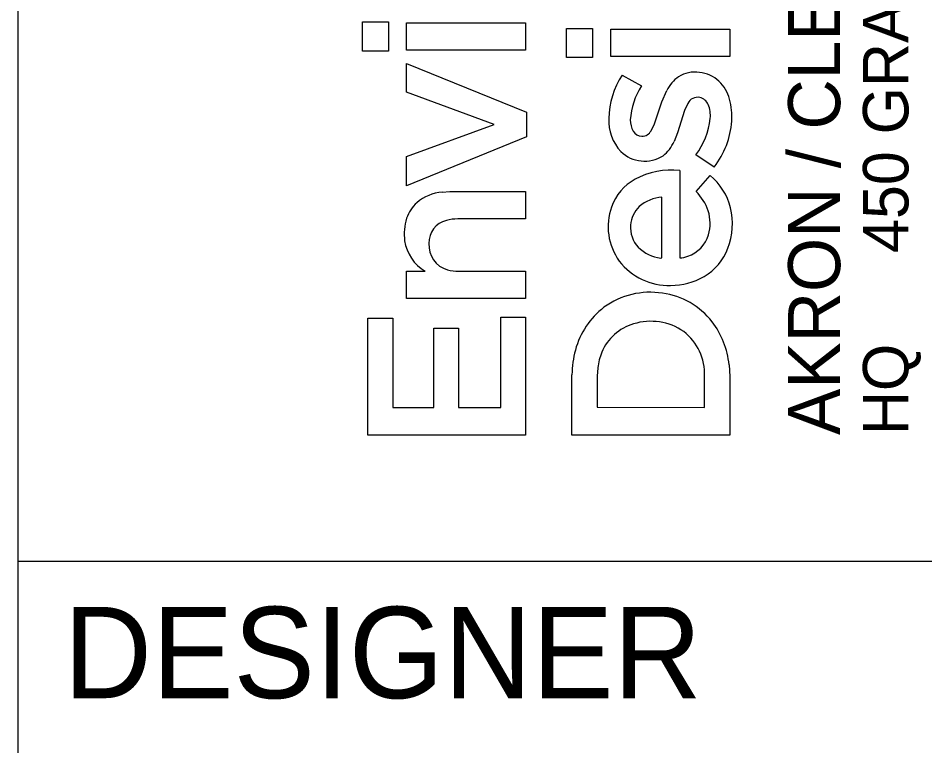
# Model space of a CAD drawing. Extents: x 0 to 34, y 0 to 22.
# Drawn here: x 32 to 32.993, y 2.798 to 3.594 of the extents above; entities that cross this region are included whole.
import ezdxf

# ---------------------------------------------------------------- set-up
doc = ezdxf.new("R2010")
doc.units = 0
doc.layers.add('SH_Border', color=7, linetype='Continuous')
doc.layers.add('SH_Data', color=7, linetype='Continuous')

msp = doc.modelspace()

# ---------------------------------------------------------------- linework, layer by layer
at = {"layer": 'SH_Border'}
for p, q in [((32, 0.5), (32, 21.5)), ((32, 3), (33.5, 3))]:
    msp.add_line(p, q, dxfattribs=at)
at = {"layer": 'SH_Data'}
for p, q in [((32.37705, 3.55818), (32.37705, 3.59026)), ((32.37705, 3.59026), (32.40543, 3.59026)), ((32.40543, 3.59026), (32.40543, 3.55818)), ((32.42542, 3.55942), (32.42542, 3.58928)), ((32.42542, 3.58928), (32.55571, 3.58928)), ((32.55571, 3.58928), (32.55571, 3.55942)), ((32.60051, 3.55111), (32.60051, 3.58319)), ((32.60051, 3.58319), (32.62889, 3.58319)), ((32.62889, 3.58319), (32.62889, 3.55111)), ((32.64888, 3.55234), (32.64888, 3.5822)), ((32.64888, 3.5822), (32.77917, 3.5822)), ((32.77917, 3.5822), (32.77917, 3.55234)), ((32.40543, 3.55818), (32.37705, 3.55818)), ((32.55571, 3.55942), (32.42542, 3.55942)), ((32.42542, 3.51327), (32.42542, 3.5446)), ((32.42542, 3.5446), (32.5567, 3.4913)), ((32.62889, 3.55111), (32.60051, 3.55111)), ((32.77917, 3.55234), (32.64888, 3.55234)), ((32.66151, 3.53207), (32.68268, 3.52025)), ((32.70483, 3.50258), (32.71036, 3.51526)), ((32.52117, 3.47798), (32.42542, 3.51327)), ((32.69675, 3.47868), (32.70483, 3.50258)), ((32.73342, 3.50101), (32.72985, 3.4933)), ((32.5567, 3.4913), (32.5567, 3.46441)), ((32.72985, 3.4933), (32.72213, 3.46882)), ((32.42542, 3.44294), (32.52117, 3.47798)), ((32.69299, 3.47117), (32.69675, 3.47868)), ((32.72213, 3.46882), (32.71822, 3.45921)), ((32.5567, 3.46441), (32.42542, 3.41086)), ((32.42542, 3.41086), (32.42542, 3.44294)), ((32.76214, 3.43141), (32.74198, 3.44469)), ((32.72453, 3.42747), (32.72463, 3.33195)), ((32.74228, 3.40465), (32.75768, 3.422)), ((32.46439, 3.40397), (32.47289, 3.40443)), ((32.47289, 3.40443), (32.55571, 3.40443)), ((32.55571, 3.40443), (32.55571, 3.37465)), ((32.70489, 3.33182), (32.70489, 3.39834)), ((32.55571, 3.37465), (32.4814, 3.37457)), ((32.70361, 3.33165), (32.70489, 3.33182)), ((32.42542, 3.31728), (32.44552, 3.31733)), ((32.42542, 3.28747), (32.42542, 3.31728)), ((32.48222, 3.31733), (32.55569, 3.31733)), ((32.55569, 3.31733), (32.55571, 3.28756)), ((32.55571, 3.28756), (32.42542, 3.28747)), ((32.52857, 3.16827), (32.52857, 3.26722)), ((32.52857, 3.26722), (32.55571, 3.26722)), ((32.55571, 3.26722), (32.55571, 3.13791)), ((32.38298, 3.13791), (32.38298, 3.26598)), ((32.38298, 3.26598), (32.41012, 3.26598)), ((32.41012, 3.26598), (32.41012, 3.16827)), ((32.45503, 3.16827), (32.45503, 3.25488)), ((32.45503, 3.25488), (32.48218, 3.25488)), ((32.48218, 3.25488), (32.48218, 3.16827)), ((32.63465, 3.21178), (32.63407, 3.2023)), ((32.77847, 3.21497), (32.77917, 3.2021)), ((32.60643, 3.13799), (32.60644, 3.204)), ((32.63407, 3.2023), (32.63407, 3.16838)), ((32.75149, 3.16834), (32.75153, 3.20239)), ((32.77917, 3.2021), (32.77917, 3.138)), ((32.41012, 3.16827), (32.45503, 3.16827)), ((32.48218, 3.16827), (32.52857, 3.16827)), ((32.63407, 3.16838), (32.75149, 3.16834)), ((32.55571, 3.13791), (32.38298, 3.13791)), ((32.77917, 3.138), (32.60643, 3.13799))]:
    msp.add_line(p, q, dxfattribs=at)
for points in [[(32.37705, 3.55818), (32.37705, 3.59026), (32.40543, 3.59026), (32.40543, 3.55818)], [(32.42542, 3.55942), (32.42542, 3.58928), (32.55571, 3.58928), (32.55571, 3.55942)], [(32.60051, 3.55111), (32.60051, 3.58319), (32.62889, 3.58319), (32.62889, 3.55111)], [(32.64888, 3.55234), (32.64888, 3.5822), (32.77917, 3.5822), (32.77917, 3.55234)], [(32.42542, 3.41086), (32.42542, 3.44294), (32.52117, 3.47798), (32.42542, 3.51327), (32.42542, 3.5446), (32.5567, 3.4913), (32.5567, 3.46441)], [(32.38298, 3.13791), (32.38298, 3.26598), (32.41012, 3.26598), (32.41012, 3.16827), (32.45503, 3.16827), (32.45503, 3.25488), (32.48218, 3.25488), (32.48218, 3.16827), (32.52857, 3.16827), (32.52857, 3.26722), (32.55571, 3.26722), (32.55571, 3.13791)]]:
    msp.add_lwpolyline(points, close=True, dxfattribs=at)
for points in [[(32.66151, 3.53207), (32.68268, 3.52025)], [(32.69299, 3.47117), (32.69675, 3.47868), (32.70483, 3.50258), (32.71036, 3.51526)], [(32.73342, 3.50101), (32.72985, 3.4933), (32.72213, 3.46882), (32.71822, 3.45921)], [(32.76214, 3.43141), (32.74198, 3.44469)], [(32.72453, 3.42747), (32.72463, 3.33195)], [(32.74228, 3.40465), (32.75768, 3.422)], [(32.46439, 3.40397), (32.47289, 3.40443), (32.55571, 3.40443), (32.55571, 3.37465), (32.4814, 3.37457)], [(32.70361, 3.33165), (32.70489, 3.33182), (32.70489, 3.39834)], [(32.42542, 3.28747), (32.42542, 3.31728), (32.44552, 3.31733)], [(32.48222, 3.31733), (32.55569, 3.31733), (32.55571, 3.28756), (32.42542, 3.28747)], [(32.77847, 3.21497), (32.77917, 3.2021), (32.77917, 3.138), (32.60643, 3.13799)], [(32.63465, 3.21178), (32.63407, 3.2023), (32.63407, 3.16838), (32.75149, 3.16834), (32.75153, 3.20239)], [(32.60643, 3.13799), (32.60644, 3.204)]]:
    msp.add_lwpolyline(points, dxfattribs=at)
for centre, radius, start, end in [((32.7406, 3.5026), 0.03263, 80.17192, 122.51969), ((32.7406, 3.5026), 0.03263, 80.17192, 122.51969), ((32.74278, 3.49824), 0.03667, 47.79344, 84.68918), ((32.74278, 3.49824), 0.03667, 47.79344, 84.68918), ((32.73636, 3.48258), 0.08973, 146.53104, 178.7571), ((32.73636, 3.48258), 0.08973, 146.53104, 178.7571), ((32.74661, 3.49713), 0.04053, 125.51182, 153.41595), ((32.74661, 3.49713), 0.04053, 125.51182, 153.41595), ((32.73788, 3.4946), 0.04267, 14.9966, 46.20632), ((32.73788, 3.4946), 0.04267, 14.9966, 46.20632), ((32.74519, 3.4789), 0.07495, 146.51121, 176.91007), ((32.74519, 3.4789), 0.07495, 146.51121, 176.91007), ((32.74384, 3.49631), 0.01143, 76.66094, 155.7053), ((32.74384, 3.49631), 0.01143, 76.66094, 155.7053), ((32.74397, 3.49511), 0.01256, 21.5098, 78.52618), ((32.74397, 3.49511), 0.01256, 21.5098, 78.52618), ((32.71044, 3.48674), 0.07121, 355.83062, 15.39138), ((32.71044, 3.48674), 0.07121, 355.83062, 15.39138), ((32.72592, 3.48766), 0.03209, 354.57264, 22.06805), ((32.72592, 3.48766), 0.03209, 354.57264, 22.06805), ((32.69666, 3.48238), 0.05005, 177.53659, 222.79318), ((32.69666, 3.48238), 0.05005, 177.53659, 222.79318), ((32.6931, 3.48233), 0.02276, 178.47474, 211.08679), ((32.6931, 3.48233), 0.02276, 178.47474, 211.08679), ((32.68248, 3.49149), 0.0757, 321.81101, 354.79685), ((32.68248, 3.49149), 0.0757, 321.81101, 354.79685), ((32.68952, 3.4882), 0.09219, 321.9777, 355.87384), ((32.68952, 3.4882), 0.09219, 321.9777, 355.87384), ((32.68331, 3.4767), 0.01148, 212.23676, 268.37769), ((32.68331, 3.4767), 0.01148, 212.23676, 268.37769), ((32.68342, 3.47589), 0.01067, 267.71603, 333.73375), ((32.68342, 3.47589), 0.01067, 267.71603, 333.73375), ((32.68098, 3.4758), 0.04077, 308.08772, 335.98736), ((32.68098, 3.4758), 0.04077, 308.08772, 335.98736), ((32.68599, 3.47535), 0.0375, 225.98539, 302.47965), ((32.68599, 3.47535), 0.0375, 225.98539, 302.47965), ((32.7152, 3.34414), 0.08384, 83.61499, 118.28755), ((32.7152, 3.34414), 0.08384, 83.61499, 118.28755), ((32.70239, 3.36906), 0.05583, 118.83082, 160.62438), ((32.70239, 3.36906), 0.05583, 118.83082, 160.62438), ((32.71744, 3.37167), 0.06443, 13.53365, 51.36148), ((32.71744, 3.37167), 0.06443, 13.53365, 51.36148), ((32.46871, 3.35428), 0.04988, 94.96958, 130.22249), ((32.46871, 3.35428), 0.04988, 94.96958, 130.22249), ((32.70785, 3.35609), 0.04235, 94.00805, 130.88169), ((32.70785, 3.35609), 0.04235, 94.00805, 130.88169), ((32.70378, 3.36556), 0.05486, 19.03571, 45.44059), ((32.70378, 3.36556), 0.05486, 19.03571, 45.44059), ((32.46348, 3.36263), 0.04015, 132.22192, 161.68183), ((32.46348, 3.36263), 0.04015, 132.22192, 161.68183), ((32.71041, 3.36612), 0.06437, 160.52012, 215.78311), ((32.71041, 3.36612), 0.06437, 160.52012, 215.78311), ((32.70048, 3.36628), 0.02985, 132.98507, 177.179), ((32.70048, 3.36628), 0.02985, 132.98507, 177.179), ((32.70635, 3.36921), 0.07579, 339.3542, 13.37853), ((32.70635, 3.36921), 0.07579, 339.3542, 13.37853), ((32.71069, 3.3697), 0.047, 344.60586, 17.007), ((32.71069, 3.3697), 0.047, 344.60586, 17.007), ((32.47872, 3.35819), 0.05601, 162.27355, 187.79185), ((32.47872, 3.35819), 0.05601, 162.27355, 187.79185), ((32.47482, 3.34867), 0.02498, 103.68646, 182.21874), ((32.47482, 3.34867), 0.02498, 103.68646, 182.21874), ((32.48108, 3.32856), 0.04601, 89.60494, 105.3284), ((32.48108, 3.32856), 0.04601, 89.60494, 105.3284), ((32.7017, 3.36503), 0.03115, 175.00126, 223.28301), ((32.7017, 3.36503), 0.03115, 175.00126, 223.28301), ((32.7224, 3.36715), 0.03504, 288.00773, 343.55078), ((32.7224, 3.36715), 0.03504, 288.00773, 343.55078), ((32.47026, 3.35802), 0.04762, 188.96199, 238.70369), ((32.47026, 3.35802), 0.04762, 188.96199, 238.70369), ((32.47735, 3.34558), 0.02756, 175.58538, 255.14386), ((32.47735, 3.34558), 0.02756, 175.58538, 255.14386), ((32.70891, 3.37363), 0.04231, 225.06188, 262.79738), ((32.70891, 3.37363), 0.04231, 225.06188, 262.79738), ((32.71894, 3.3652), 0.0626, 300.94269, 338.73225), ((32.71894, 3.3652), 0.0626, 300.94269, 338.73225), ((32.71253, 3.37054), 0.06872, 217.74516, 271.65431), ((32.71253, 3.37054), 0.06872, 217.74516, 271.65431), ((32.72474, 3.35216), 0.02021, 269.7003, 294.8711), ((32.72474, 3.35216), 0.02021, 269.7003, 294.8711), ((32.48183, 3.35948), 0.04215, 254.09162, 270.52835), ((32.48183, 3.35948), 0.04215, 254.09162, 270.52835), ((32.71549, 3.37241), 0.07056, 269.20477, 300.33412), ((32.71549, 3.37241), 0.07056, 269.20477, 300.33412), ((32.69229, 3.20792), 0.08641, 81.19402, 125.99844), ((32.69229, 3.20792), 0.08641, 81.19402, 125.99844), ((32.69458, 3.21132), 0.08272, 37.85208, 82.40204), ((32.69458, 3.21132), 0.08272, 37.85208, 82.40204), ((32.69387, 3.20893), 0.08654, 127.23621, 165.14796), ((32.69387, 3.20893), 0.08654, 127.23621, 165.14796), ((32.68893, 3.20782), 0.05398, 106.18808, 157.38609), ((32.68893, 3.20782), 0.05398, 106.18808, 157.38609), ((32.69279, 3.19862), 0.06389, 55.67272, 107.20935), ((32.69279, 3.19862), 0.06389, 55.67272, 107.20935), ((32.68586, 3.20567), 0.09308, 5.73329, 37.30396), ((32.68586, 3.20567), 0.09308, 5.73329, 37.30396), ((32.69291, 3.20499), 0.05867, 357.46616, 52.26647), ((32.69291, 3.20499), 0.05867, 357.46616, 52.26647), ((32.71426, 3.20281), 0.10783, 164.7861, 179.37039), ((32.71426, 3.20281), 0.10783, 164.7861, 179.37039), ((32.69829, 3.20389), 0.06412, 157.35705, 172.92755), ((32.69829, 3.20389), 0.06412, 157.35705, 172.92755)]:
    msp.add_arc(centre, radius, start, end, dxfattribs=at)

# ---------------------------------------------------------------- texts
for s, height, p in [('450 GRANT ST., AKRON, OH  44311', 0.0498462, (32.97489, 3.33738)), ('AKRON / CLEVELAND / COLUMBUS', 0.056969, (32.90012, 3.138)), ('HQ ', 0.049846, (32.97489, 3.138))]:
    msp.add_text(s, height=height, rotation=90, dxfattribs=at).set_placement(p)
msp.add_text('DESIGNER', height=0.1, dxfattribs=at).set_placement((32.05, 2.85))

doc.saveas('drawing.dxf')
